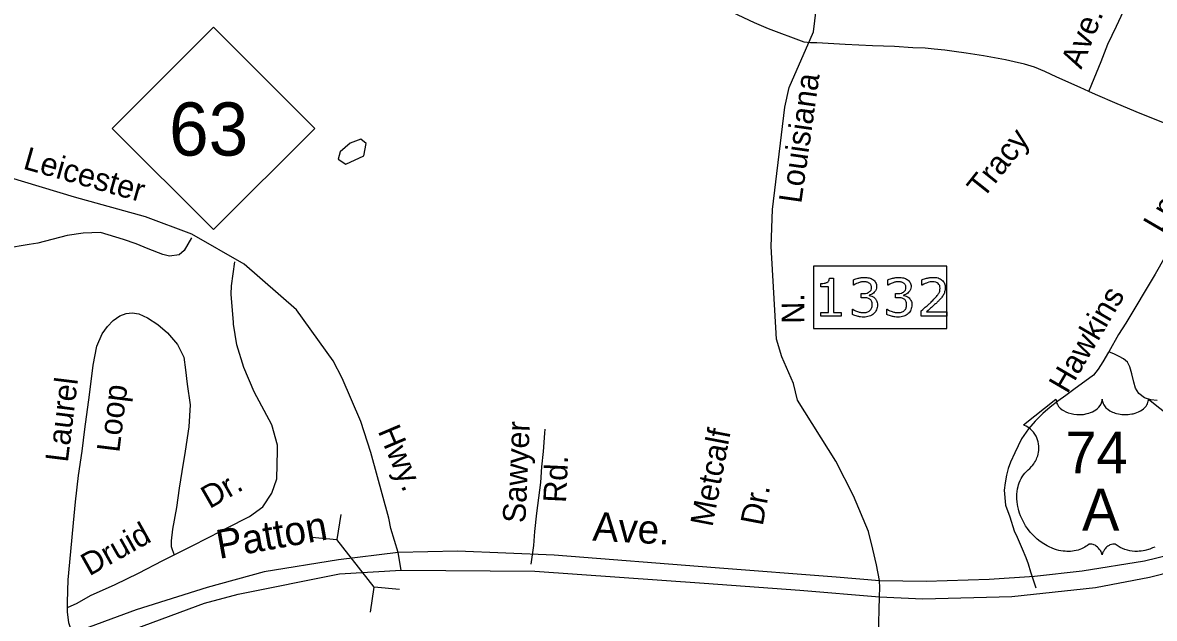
# Model space of a CAD drawing. Extents: x 925297 to 940193, y 663541 to 689899.
# Drawn here: x 927990 to 928734, y 688722 to 689114 of the extents above; entities that cross this region are included whole.
import ezdxf

# ---------------------------------------------------------------- set-up
doc = ezdxf.new("R2010")
doc.units = 0
doc.layers.add('Default', color=7, linetype='Continuous')

msp = doc.modelspace()

# ---------------------------------------------------------------- linework, layer by layer
at = {"layer": 'Default'}
for p, q in [((928510.17, 688912.75), (928597.77, 688912.75)), ((928199, 688790.25), (928196.57, 688773.77)), ((928179.98, 688775.3), (928196.57, 688773.77)), ((928221.08, 688742.57), (928196.57, 688773.77)), ((928218.65, 688726.09), (928221.08, 688742.57)), ((928237.67, 688741.04), (928221.08, 688742.57))]:
    msp.add_line(p, q, dxfattribs=at)
for points in [[(928553.43, 688746.59), (928553.42, 688746.82), (928551.56, 688757.26), (928549.12, 688767.46), (928546.36, 688779.02), (928536.39, 688802.59), (928524.77, 688825.46), (928499.45, 688865.61), (928496.98, 688876.49), (928489.25, 688893.97), (928485.62, 688905.73), (928482.24, 688966.7), (928483.12, 688991.03), (928491.1, 689058.41), (928493.98, 689071.15), (928510.13, 689107.78), (928516.9, 689163.96), (928516.9, 689174), (928519.56, 689192.85), (928521.72, 689208.23), (928534.15, 689242.18), (928543.89, 689279.85)], [(928508.05, 689100.68), (928504.03, 689101.06), (928480.39, 689109.85), (928471.34, 689113.75), (928460.49, 689118.96), (928434.8, 689132.28), (928416.96, 689142.45), (928403.99, 689148.68), (928399.36, 689150.58), (928393.92, 689152)], [(928691.32, 689068.56), (928693.22, 689073.5), (928699.25, 689088.38), (928703.82, 689099.78), (928709.44, 689111.57), (928714.11, 689121.39), (928716.27, 689126.54), (928717.98, 689130.56)], [(928691.32, 689068.56), (928685.45, 689071.18), (928670.25, 689078.11), (928662.18, 689081.76), (928655.43, 689084.7), (928648.91, 689086.59), (928642.01, 689088.25), (928636.33, 689089.41), (928621.9, 689092.05), (928610.45, 689093.88), (928602.64, 689095), (928596.53, 689095.87), (928589.38, 689096.58), (928583.55, 689097.06), (928575.37, 689097.42), (928563.31, 689098.24), (928548.86, 689098.75), (928531.01, 689099.61), (928512.3, 689100.62), (928508.05, 689100.68)], [(928781.78, 689030.89), (928772.58, 689034.71), (928752.53, 689042.9), (928738.88, 689048.57), (928724.95, 689054.2), (928709.93, 689060.53), (928695.5, 689066.7), (928691.32, 689068.56)], [(928236.88, 688765.2), (928232.1, 688781.02), (928230.66, 688787.96), (928218.78, 688831.18), (928212.29, 688851.46), (928200.05, 688880.06), (928193.98, 688891.33), (928170.04, 688925.05), (928135.6, 688955.05), (928101.08, 688974.71), (928070.48, 688986.23), (928023.85, 688999.09), (927958.24, 689018.82), (927938.3, 689025.76), (927916.04, 689035.88), (927902.17, 689042.54), (927888.82, 689051.95)], [(928202.41, 689020.76), (928214.23, 689026.34), (928215.7, 689034.3), (928212.2, 689037.22), (928205.31, 689034.67), (928198.7, 689028.9), (928197.33, 689024.14), (928202.41, 689020.76)], [(928781.78, 689030.89), (928779.83, 689026.93), (928772.94, 689013.2), (928752.24, 688978.84), (928734.93, 688948.53), (928715.5, 688916.16), (928710.79, 688908.8), (928704.29, 688897.35)], [(928100.89, 688972.23), (928095.98, 688964.04), (928092.63, 688961.13), (928086.38, 688960.18), (928081.95, 688961.27), (928072.44, 688965.18), (928064.49, 688968.33), (928056.18, 688971.26), (928040.92, 688975.78), (928029.5, 688975.39), (928019.16, 688973.8), (927999.75, 688968.86), (927994.02, 688967.88), (927978.53, 688965.24), (927965.99, 688964.64), (927947.34, 688966.13), (927929.55, 688966.84), (927907.09, 688967.83), (927890.28, 688969.31), (927872.89, 688972.01), (927826.57, 688975.7), (927819.02, 688976.15), (927814.25, 688975.03)], [(928128.5, 688916.64), (928127.04, 688935.36), (928127.19, 688940.65), (928129.36, 688956.61)], [(928510.17, 688912.75), (928597.77, 688912.75), (928597.77, 688953.75), (928510.17, 688953.75), (928510.17, 688912.75)], [(928520.67, 688945.83), (928523.27, 688945.83), (928523.27, 688923.3), (928528.37, 688923.3), (928528.37, 688920.75)], [(928536.5, 688941.2), (928536.33, 688941.2), (928536.33, 688944.7)], [(928559.16, 688941.2), (928558.99, 688941.2), (928558.99, 688944.7)], [(928581.61, 688941.2), (928581.44, 688941.2), (928581.44, 688944.72)], [(928528.37, 688920.75), (928514.84, 688920.75), (928514.84, 688923.3), (928520.04, 688923.3), (928520.04, 688940.05), (928514.84, 688940.05), (928514.84, 688942.34)], [(928542.91, 688932.93), (928541.4, 688932.93), (928541.4, 688935.71), (928542.57, 688935.71)], [(928546.63, 688934.65), (928546.63, 688934.42)], [(928565.57, 688932.93), (928564.05, 688932.93), (928564.05, 688935.71), (928565.23, 688935.71)], [(928569.29, 688934.65), (928569.29, 688934.42)], [(928019.24, 688729.06), (928019.19, 688732.65), (928019.65, 688747.21), (928021.43, 688765.86), (928023.32, 688784.86), (928024.59, 688798.68), (928026.47, 688815.97), (928028.85, 688831.96), (928030.65, 688846.36), (928033.72, 688869.06), (928036.14, 688888.59), (928038.57, 688900.98), (928042.05, 688909.24), (928045.63, 688914.01), (928049.29, 688917.84), (928053.81, 688920.98), (928057.97, 688922.49), (928061.76, 688922.9), (928066.27, 688922.39), (928071.97, 688919.77), (928078.75, 688915.24), (928085.05, 688909.79), (928091.68, 688902.1), (928095.71, 688893.77), (928097.01, 688885.38), (928098.11, 688876.05), (928099.9, 688862.56), (928099.14, 688847.89), (928096.73, 688831.86), (928094.46, 688818.59), (928092.78, 688807.7), (928090.91, 688794.98), (928088.42, 688780.74), (928087.5, 688773.07), (928087.46, 688769.32), (928088.03, 688767.16), (928089.47, 688763.73)], [(928535.62, 688921.79), (928535.62, 688925.3), (928535.87, 688925.3)], [(928558.28, 688921.79), (928558.28, 688925.3), (928558.53, 688925.3)], [(928597.77, 688920.75), (928580.83, 688920.75), (928580.83, 688924.28)], [(928584.31, 688923.65), (928597.77, 688923.65), (928597.77, 688920.75)], [(928157.45, 688832.4), (928157.54, 688836), (928153.66, 688849.32), (928142.05, 688871.07), (928135.35, 688887.08), (928130.78, 688901.96), (928128.58, 688915.5), (928128.5, 688916.64)], [(928704.29, 688897.35), (928704.11, 688897.04), (928700.32, 688890.65), (928697.27, 688885.83), (928694.18, 688882.02), (928688.57, 688877.85), (928682.2, 688873.15), (928676.02, 688868.7), (928670.91, 688864.97), (928665.88, 688861.01), (928660.91, 688856.65), (928655.82, 688851.74), (928651.45, 688846.64), (928647.02, 688839.98), (928642.43, 688830.89), (928639.66, 688824.76), (928638.11, 688820.58), (928637.03, 688816.08), (928636.09, 688811.07), (928635.61, 688806.39), (928636.28, 688796.47), (928639.22, 688788.81), (928642.19, 688779.61), (928644.17, 688775.37), (928647.28, 688767.61), (928649.69, 688762.06), (928651.25, 688757.89), (928652.92, 688752.63), (928656.35, 688742.03)], [(928736.25, 688865.41), (928731.95, 688865.82), (928727.94, 688867.11), (928724, 688869.87), (928721.93, 688873.45), (928720.8, 688877.33), (928719.5, 688882.78), (928718.26, 688887.35), (928716.55, 688890.46), (928713.92, 688892.78), (928711.17, 688894.26), (928707.99, 688895.69), (928704.29, 688897.35)], [(929190.42, 688875.58), (929149.29, 688864.98), (929112.36, 688855.44), (929052.19, 688840.84), (929001.1, 688828.77), (928863.79, 688792.71), (928727.82, 688759.49), (928686.82, 688753.06), (928655.56, 688749.51), (928625.66, 688747.58), (928584.13, 688746.27), (928553.43, 688746.59)], [(928734.6, 688768.9), (928733.14, 688768.27), (928731.26, 688767.55), (928728.12, 688766.69), (928726.98, 688766.45), (928725.63, 688766.25), (928724.36, 688766.12), (928723.13, 688766.05), (928721.47, 688766.05), (928719.83, 688766.17), (928718.27, 688766.4), (928716.65, 688766.74), (928714.96, 688767.24), (928713.42, 688767.84), (928711.86, 688768.61), (928709.23, 688770.27), (928708.47, 688770.67), (928708.04, 688770.78), (928707.03, 688770.83), (928706.07, 688770.63), (928705.09, 688770.24), (928704.5, 688769.93), (928703.72, 688769.41), (928703.12, 688768.94), (928702.39, 688768.25), (928701.89, 688767.67), (928701.5, 688767.22), (928700.76, 688766.05), (928700.5, 688765.49), (928700.22, 688764.78), (928699.98, 688763.73), (928699.65, 688765.05), (928699.26, 688765.93), (928698.8, 688766.69), (928698.33, 688767.35), (928697.59, 688768.21), (928696.93, 688768.85), (928696.12, 688769.5), (928695.27, 688770.02), (928694.59, 688770.37), (928693.96, 688770.61), (928693.19, 688770.8), (928692.57, 688770.85), (928692.05, 688770.83), (928691.34, 688770.67), (928690.38, 688769.98), (928689.47, 688769.35), (928688.48, 688768.74), (928687.3, 688768.11), (928686.43, 688767.7), (928685.4, 688767.3), (928684.2, 688766.9), (928682.89, 688766.56), (928681.55, 688766.3), (928680.37, 688766.11), (928679.1, 688766), (928677.96, 688765.96), (928676.77, 688765.97), (928675.65, 688766.06), (928674.36, 688766.17), (928672.75, 688766.41), (928671.42, 688766.71), (928670.01, 688767.09), (928668.57, 688767.54), (928667.03, 688768.13), (928665.09, 688768.97), (928663.75, 688769.66), (928661.63, 688770.88), (928659.14, 688772.6), (928657.27, 688774.12), (928655.89, 688775.37), (928653.87, 688777.43), (928652.68, 688778.77), (928650.82, 688781.18), (928649.63, 688782.93), (928648.86, 688784.21), (928647.73, 688786.27), (928647.1, 688787.56), (928646.3, 688789.45), (928645.67, 688791.17), (928645.14, 688792.8), (928644.86, 688793.84), (928644.46, 688795.66), (928644.21, 688796.96), (928643.97, 688798.73), (928643.84, 688800.6), (928643.82, 688802.32), (928643.86, 688803.75), (928644.02, 688805.42), (928644.31, 688807.19), (928644.65, 688808.71), (928644.95, 688809.81), (928645.4, 688811.14), (928646, 688812.61), (928646.7, 688814.01), (928647.38, 688815.18), (928648.22, 688816.44), (928649.04, 688817.5), (928650.13, 688818.69), (928651.26, 688819.77), (928652.3, 688820.61), (928653.53, 688821.81), (928654.17, 688822.54), (928654.94, 688823.56), (928655.55, 688824.5), (928656.04, 688825.34), (928656.69, 688826.59), (928657.08, 688827.51), (928657.57, 688828.95), (928657.81, 688829.95), (928658.06, 688831.24), (928658.23, 688832.46), (928658.29, 688833.98), (928658.25, 688835.24), (928658.09, 688836.71), (928657.81, 688838.12), (928657.48, 688839.35), (928656.95, 688840.75), (928656.47, 688841.78), (928655.65, 688843.18), (928654.75, 688844.47), (928653.82, 688845.53), (928652.87, 688846.47), (928651.97, 688847.17), (928651.11, 688847.79), (928650.03, 688848.44), (928648.99, 688848.95), (928648.33, 688849.22), (928669.59, 688866.15), (928669.64, 688865.27), (928669.86, 688864.23), (928670.02, 688863.69), (928670.51, 688862.66), (928671.31, 688861.44), (928672.44, 688860.25), (928673.7, 688859.2), (928674.56, 688858.65), (928676.01, 688857.87), (928677.65, 688857.18), (928679.49, 688856.65), (928681.36, 688856.28), (928683.4, 688856.05), (928685.42, 688856.01), (928687.61, 688856.18), (928690.02, 688856.64), (928691.13, 688856.93), (928692.38, 688857.36), (928693.53, 688857.83), (928694.8, 688858.51), (928695.82, 688859.17), (928696.61, 688859.74), (928697.74, 688860.82), (928698.64, 688861.94), (928699.02, 688862.57), (928699.34, 688863.17), (928699.79, 688864.45), (928699.92, 688865.02), (928700.01, 688866.2), (928700.08, 688865.21), (928700.18, 688864.59), (928700.34, 688863.99), (928700.59, 688863.35), (928701.05, 688862.44), (928701.55, 688861.69), (928702.5, 688860.57), (928703.09, 688860.02), (928703.63, 688859.58), (928705.07, 688858.59), (928706.76, 688857.73), (928707.59, 688857.37), (928708.44, 688857.07), (928709.52, 688856.74), (928710.64, 688856.48), (928711.74, 688856.29), (928712.87, 688856.13), (928714.03, 688856.04), (928714.97, 688856.01), (928716.12, 688856.03), (928717.19, 688856.09), (928718.28, 688856.21), (928719.49, 688856.42), (928720.45, 688856.63), (928721.73, 688856.97), (928722.89, 688857.38), (928723.91, 688857.82), (928725.22, 688858.51), (928726.29, 688859.18), (928727.07, 688859.81), (928728, 688860.66), (928728.88, 688861.68), (928729.39, 688862.42), (928729.76, 688863.19), (928730.09, 688863.99), (928730.3, 688864.84), (928730.4, 688865.58), (928730.42, 688866.22), (928751.68, 688849.28)], [(928324.4, 688757.65), (928326.01, 688769.87), (928326.7, 688779.14), (928327.97, 688791.17), (928330.66, 688811.4), (928331.39, 688821.73), (928332.43, 688831.8), (928333.41, 688843.9), (928333.56, 688846.33)], [(928089.47, 688763.73), (928101.71, 688769.95), (928120.49, 688779.55), (928123.91, 688781.3), (928138.98, 688789), (928147.71, 688795.35), (928153.8, 688804.32), (928157, 688813.85), (928157.45, 688832.4)], [(928553.42, 688736.09), (928582.01, 688734.9), (928640.54, 688736.24), (928695.65, 688742.2), (928731.09, 688749.06), (929027.74, 688824.35)], [(928553.43, 688746.59), (928524.96, 688748.98), (928445.36, 688755.29), (928339.51, 688763.64), (928275.87, 688766.17), (928236.88, 688765.2)], [(928236.88, 688765.2), (928197.65, 688760.37), (928148.73, 688752.64), (928111.1, 688742.35), (928064.45, 688727.61), (928020.95, 688711.49), (927997.19, 688699.27), (927957.24, 688676.7), (927843.22, 688597.56), (927755.38, 688536.1), (927715.75, 688509.34), (927710.65, 688498.84)], [(928019.24, 688729.06), (928025.61, 688731.88), (928034.37, 688736.96), (928050.62, 688744.3), (928065.97, 688751.72), (928082.07, 688759.97), (928089.47, 688763.73)], [(928238.86, 688753.74), (928236.88, 688765.2)], [(927710.65, 688498.84), (927723.22, 688503.35), (927740.94, 688514.64), (927877, 688608.54), (927962.31, 688666.83), (928028.27, 688701.9), (928109.47, 688731.89), (928131.56, 688737.94), (928198.26, 688751.16), (928238.86, 688753.74)], [(928238.86, 688753.74), (928326.7, 688753.06), (928438.06, 688745), (928501.11, 688740.49), (928553.42, 688736.09)], [(928553.42, 688736.09), (928553.6, 688742.26), (928553.43, 688746.59)], [(928549.65, 688683.45), (928552.82, 688710.77), (928553.42, 688736.09)], [(928025.14, 688703.27), (928020.07, 688719.03), (928019.28, 688726.34), (928019.24, 688729.06)]]:
    msp.add_lwpolyline(points, dxfattribs=at)
msp.add_lwpolyline([(928048.69, 689044.38), (928115.29, 689110.98), (928181.89, 689044.38), (928115.29, 688977.78)], close=True, dxfattribs=at)
for points in [[(928514.84, 688942.34), (928515.9, 688942.34), (928517.11, 688942.52), (928518.32, 688942.69), (928518.94, 688943.03), (928519.71, 688943.45), (928520.15, 688944.09), (928520.6, 688944.74), (928520.67, 688945.83)], [(928536.33, 688944.7), (928537.53, 688945.29), (928539.52, 688945.78), (928541.51, 688946.28), (928543.38, 688946.28), (928545.21, 688946.28), (928546.6, 688945.94), (928548, 688945.61), (928549.13, 688944.87), (928550.34, 688944.06), (928550.96, 688942.92), (928551.58, 688941.78), (928551.58, 688940.25), (928551.58, 688938.17), (928550.11, 688936.61), (928548.64, 688935.06), (928546.63, 688934.65)], [(928558.99, 688944.7), (928560.18, 688945.29), (928562.18, 688945.78), (928564.17, 688946.28), (928566.03, 688946.28), (928567.87, 688946.28), (928569.26, 688945.94), (928570.66, 688945.61), (928571.78, 688944.87), (928572.99, 688944.06), (928573.61, 688942.92), (928574.24, 688941.78), (928574.24, 688940.25), (928574.24, 688938.17), (928572.76, 688936.61), (928571.29, 688935.06), (928569.29, 688934.65)], [(928581.44, 688944.72), (928582.64, 688945.31), (928584.63, 688945.79), (928586.62, 688946.28), (928588.49, 688946.28), (928592.34, 688946.28), (928594.52, 688944.43), (928596.71, 688942.57), (928596.71, 688939.4), (928596.71, 688937.97), (928596.35, 688936.74), (928595.99, 688935.51), (928595.28, 688934.4), (928594.63, 688933.36), (928593.74, 688932.35), (928592.86, 688931.35), (928591.6, 688930.12), (928589.8, 688928.36), (928587.89, 688926.71), (928585.97, 688925.06), (928584.31, 688923.65)], [(928542.57, 688935.71), (928545.13, 688935.71), (928546.65, 688936.78), (928548.17, 688937.84), (928548.17, 688939.9), (928548.17, 688940.81), (928547.78, 688941.49), (928547.4, 688942.17), (928546.71, 688942.61), (928545.99, 688943.04), (928545.16, 688943.21), (928544.34, 688943.38), (928543.3, 688943.38), (928541.7, 688943.38), (928539.9, 688942.81), (928538.1, 688942.24), (928536.5, 688941.2)], [(928565.23, 688935.71), (928567.79, 688935.71), (928569.31, 688936.78), (928570.83, 688937.84), (928570.83, 688939.9), (928570.83, 688940.81), (928570.44, 688941.49), (928570.05, 688942.17), (928569.37, 688942.61), (928568.64, 688943.04), (928567.82, 688943.21), (928566.99, 688943.38), (928565.95, 688943.38), (928564.36, 688943.38), (928562.56, 688942.81), (928560.76, 688942.24), (928559.16, 688941.2)], [(928580.83, 688924.28), (928582.6, 688925.79), (928584.37, 688927.3), (928586.15, 688928.82), (928587.68, 688930.31), (928590.91, 688933.43), (928592.11, 688935.27), (928593.3, 688937.1), (928593.3, 688939.24), (928593.3, 688941.18), (928592.01, 688942.28), (928590.72, 688943.38), (928588.42, 688943.38), (928586.88, 688943.38), (928585.1, 688942.84), (928583.31, 688942.31), (928581.61, 688941.2)], [(928550.24, 688932.79), (928551.05, 688932.07), (928551.57, 688930.97), (928552.09, 688929.88), (928552.09, 688928.15), (928552.09, 688926.44), (928551.47, 688925.01), (928550.85, 688923.58), (928549.72, 688922.52), (928548.46, 688921.34), (928546.76, 688920.78), (928545.06, 688920.22), (928543.02, 688920.22), (928540.94, 688920.22), (928538.93, 688920.71), (928536.91, 688921.21), (928535.62, 688921.79)], [(928535.87, 688925.3), (928537.3, 688924.36), (928539.23, 688923.74), (928541.17, 688923.12), (928542.97, 688923.12), (928544.03, 688923.12), (928545.22, 688923.47), (928546.41, 688923.82), (928547.15, 688924.51), (928547.92, 688925.25), (928548.3, 688926.15), (928548.68, 688927.04), (928548.68, 688928.4), (928548.68, 688929.75), (928548.25, 688930.63), (928547.82, 688931.52), (928547.07, 688932.02), (928546.31, 688932.54), (928545.23, 688932.74), (928544.16, 688932.93), (928542.91, 688932.93)], [(928546.63, 688934.42), (928547.44, 688934.29), (928548.48, 688933.86), (928549.52, 688933.43), (928550.24, 688932.79)], [(928572.9, 688932.79), (928573.71, 688932.07), (928574.23, 688930.97), (928574.75, 688929.88), (928574.75, 688928.15), (928574.75, 688926.44), (928574.13, 688925.01), (928573.5, 688923.58), (928572.38, 688922.52), (928571.12, 688921.34), (928569.42, 688920.78), (928567.71, 688920.22), (928565.68, 688920.22), (928563.6, 688920.22), (928561.58, 688920.71), (928559.57, 688921.21), (928558.28, 688921.79)], [(928558.53, 688925.3), (928559.96, 688924.36), (928561.89, 688923.74), (928563.82, 688923.12), (928565.62, 688923.12), (928566.68, 688923.12), (928567.88, 688923.47), (928569.07, 688923.82), (928569.81, 688924.51), (928570.58, 688925.25), (928570.96, 688926.15), (928571.34, 688927.04), (928571.34, 688928.4), (928571.34, 688929.75), (928570.91, 688930.63), (928570.48, 688931.52), (928569.72, 688932.02), (928568.97, 688932.54), (928567.89, 688932.74), (928566.81, 688932.93), (928565.57, 688932.93)], [(928569.29, 688934.42), (928570.1, 688934.29), (928571.14, 688933.86), (928572.18, 688933.43), (928572.9, 688932.79)]]:
    msp.add_open_spline(points, degree=3, dxfattribs=at)

# ---------------------------------------------------------------- texts
for s, height, rotation, p in [('Ave.', 15, 68.36504, (928686.26, 689082.79)), ('Louisiana', 15, 81.89554, (928502, 688994.5)), ('Tracy', 15, 51.44985, (928621.62, 688997.56)), ('Leicester', 15, 344.11932, (927989.39, 689017.98)), ('Ln.', 15, 59.72093, (928739.12, 688974.83)), ('Hawkins', 15, 59.72093, (928677.01, 688869.16)), ('N.', 15, 90.56487, (928504.16, 688915.88)), ('Laurel', 15, 82.99854, (928019.47, 688824.2)), ('Loop', 15, 82.99854, (928053.35, 688830.69)), ('Hwy.', 15, 292.89774, (928223.23, 688845.23)), ('Sawyer', 15, 87.39619, (928320.51, 688784.44)), ('Metcalf', 15, 79.18458, (928443.58, 688781.66)), ('Rd.', 15, 87.39619, (928347.22, 688797.75)), ('Dr.', 15, 29.87194, (928112.75, 688793.78)), ('Dr.', 15, 79.18458, (928476.61, 688782.35)), ('Patton', 19, 10.18005, (928119.01, 688761.02)), ('Ave.', 19, 357.00608, (928364.37, 688773.09)), ('Druid', 15, 29.24286, (928033.6, 688749.5))]:
    msp.add_text(s, height=height, rotation=rotation, dxfattribs=at).set_placement(p)
for s, height, p in [('63', 35, (928086.11, 689026.44)), ('74', 27.5, (928675.78, 688817.34)), ('A', 27.5, (928686.75, 688779.75))]:
    msp.add_text(s, height=height, dxfattribs=at).set_placement(p)

doc.saveas('drawing.dxf')
